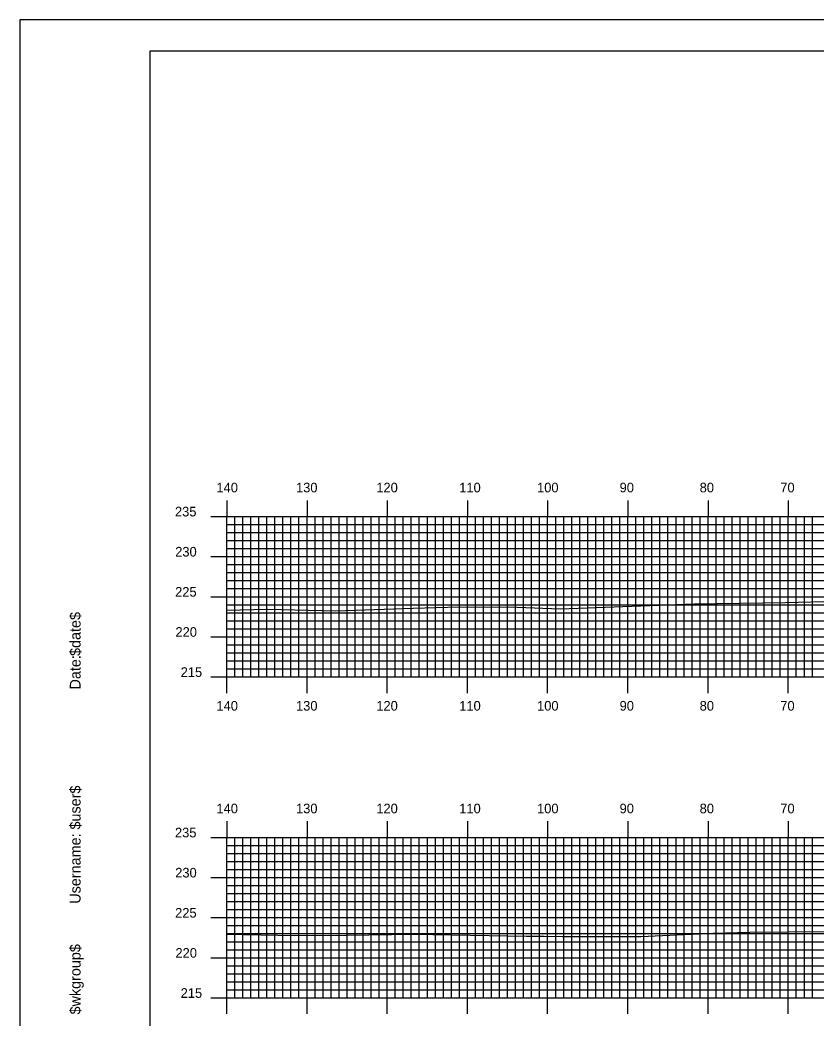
# Model space of a CAD drawing. Extents: x 1804684 to 1805027, y 442591 to 442811.
# Drawn here: x 1804683.9 to 1804783.1, y 442686.2 to 442810.5 of the extents above; entities that cross this region are included whole.
import ezdxf

# ---------------------------------------------------------------- set-up
doc = ezdxf.new("R2010")
doc.units = 0
for name, color, linetype in [('BORDER', 7, 'Continuous'), ('H_V ANNOTATION', 7, 'Continuous'), ('MAJOR', 7, 'Continuous'), ('MINOR', 7, 'Continuous'), ('PLOT BOUNDARY', 7, 'Continuous'), ('S_Roadway_Centerline', 7, 'Continuous')]:
    doc.layers.add(name, color=color, linetype=linetype)

msp = doc.modelspace()

# ---------------------------------------------------------------- linework, layer by layer
at = {"layer": 'BORDER'}
msp.add_lwpolyline([(1804700.08, 442596.67), (1805020.08, 442596.67), (1805020.08, 442806.67), (1804700.08, 442806.67)], close=True, dxfattribs=at)
at = {"layer": 'MAJOR'}
for p, q in [((1804709.68, 442750.67), (1804709.68, 442748.67)), ((1804719.68, 442750.67), (1804719.68, 442748.67)), ((1804729.68, 442750.67), (1804729.68, 442748.67)), ((1804739.68, 442750.67), (1804739.68, 442748.67)), ((1804749.68, 442750.67), (1804749.68, 442748.67)), ((1804759.68, 442750.67), (1804759.68, 442748.67)), ((1804769.68, 442750.67), (1804769.68, 442748.67)), ((1804779.68, 442750.67), (1804779.68, 442748.67)), ((1804707.68, 442748.67), (1804709.68, 442748.67)), ((1804709.68, 442748.67), (1804989.68, 442748.67)), ((1804709.68, 442728.67), (1804709.68, 442748.67)), ((1804709.68, 442728.67), (1804709.68, 442748.67)), ((1804709.68, 442748.67), (1804989.68, 442748.67)), ((1804719.68, 442728.67), (1804719.68, 442748.67)), ((1804729.68, 442728.67), (1804729.68, 442748.67)), ((1804739.68, 442728.67), (1804739.68, 442748.67)), ((1804749.68, 442728.67), (1804749.68, 442748.67)), ((1804759.68, 442728.67), (1804759.68, 442748.67)), ((1804769.68, 442728.67), (1804769.68, 442748.67)), ((1804779.68, 442728.67), (1804779.68, 442748.67)), ((1804707.68, 442743.67), (1804709.68, 442743.67)), ((1804709.68, 442743.67), (1804989.68, 442743.67)), ((1804707.68, 442738.67), (1804709.68, 442738.67)), ((1804709.68, 442738.67), (1804989.68, 442738.67)), ((1804707.68, 442733.67), (1804709.68, 442733.67)), ((1804709.68, 442733.67), (1804989.68, 442733.67)), ((1804707.68, 442728.67), (1804709.68, 442728.67)), ((1804709.68, 442728.67), (1804989.68, 442728.67)), ((1804709.68, 442728.67), (1804989.68, 442728.67)), ((1804709.68, 442726.66), (1804709.68, 442728.67)), ((1804719.68, 442726.66), (1804719.68, 442728.67)), ((1804729.68, 442726.66), (1804729.68, 442728.67)), ((1804739.68, 442726.66), (1804739.68, 442728.67)), ((1804749.68, 442726.66), (1804749.68, 442728.67)), ((1804759.68, 442726.66), (1804759.68, 442728.67)), ((1804769.68, 442726.66), (1804769.68, 442728.67)), ((1804779.68, 442726.66), (1804779.68, 442728.67)), ((1804709.68, 442710.67), (1804709.68, 442708.67)), ((1804719.68, 442710.67), (1804719.68, 442708.67)), ((1804729.68, 442710.67), (1804729.68, 442708.67)), ((1804739.68, 442710.67), (1804739.68, 442708.67)), ((1804749.68, 442710.67), (1804749.68, 442708.67)), ((1804759.68, 442710.67), (1804759.68, 442708.67)), ((1804769.68, 442710.67), (1804769.68, 442708.67)), ((1804779.68, 442710.67), (1804779.68, 442708.67)), ((1804707.68, 442708.67), (1804709.68, 442708.67)), ((1804709.68, 442708.67), (1804989.68, 442708.67)), ((1804709.68, 442688.67), (1804709.68, 442708.67)), ((1804709.68, 442688.67), (1804709.68, 442708.67)), ((1804709.68, 442708.67), (1804989.68, 442708.67)), ((1804719.68, 442688.67), (1804719.68, 442708.67)), ((1804729.68, 442688.67), (1804729.68, 442708.67)), ((1804739.68, 442688.67), (1804739.68, 442708.67)), ((1804749.68, 442688.67), (1804749.68, 442708.67)), ((1804759.68, 442688.67), (1804759.68, 442708.67)), ((1804769.68, 442688.67), (1804769.68, 442708.67)), ((1804779.68, 442688.67), (1804779.68, 442708.67)), ((1804707.68, 442703.67), (1804709.68, 442703.67)), ((1804709.68, 442703.67), (1804989.68, 442703.67)), ((1804707.68, 442698.67), (1804709.68, 442698.67)), ((1804709.68, 442698.67), (1804989.68, 442698.67)), ((1804707.68, 442693.67), (1804709.68, 442693.67)), ((1804709.68, 442693.67), (1804989.68, 442693.67)), ((1804707.68, 442688.67), (1804709.68, 442688.67)), ((1804709.68, 442688.67), (1804989.68, 442688.67)), ((1804709.68, 442688.67), (1804989.68, 442688.67)), ((1804709.68, 442686.66), (1804709.68, 442688.67)), ((1804719.68, 442686.66), (1804719.68, 442688.67)), ((1804729.68, 442686.66), (1804729.68, 442688.67)), ((1804739.68, 442686.66), (1804739.68, 442688.67)), ((1804749.68, 442686.66), (1804749.68, 442688.67)), ((1804759.68, 442686.66), (1804759.68, 442688.67)), ((1804769.68, 442686.66), (1804769.68, 442688.67)), ((1804779.68, 442686.66), (1804779.68, 442688.67))]:
    msp.add_line(p, q, dxfattribs=at)
at = {"layer": 'MINOR'}
for p, q in [((1804710.68, 442728.67), (1804710.68, 442748.67)), ((1804711.68, 442728.67), (1804711.68, 442748.67)), ((1804712.68, 442728.67), (1804712.68, 442748.67)), ((1804713.68, 442728.67), (1804713.68, 442748.67)), ((1804714.68, 442728.67), (1804714.68, 442748.67)), ((1804715.68, 442728.67), (1804715.68, 442748.67)), ((1804716.68, 442728.67), (1804716.68, 442748.67)), ((1804717.68, 442728.67), (1804717.68, 442748.67)), ((1804718.68, 442728.67), (1804718.68, 442748.67)), ((1804720.68, 442728.67), (1804720.68, 442748.67)), ((1804721.68, 442728.67), (1804721.68, 442748.67)), ((1804722.68, 442728.67), (1804722.68, 442748.67)), ((1804723.68, 442728.67), (1804723.68, 442748.67)), ((1804724.68, 442728.67), (1804724.68, 442748.67)), ((1804725.68, 442728.67), (1804725.68, 442748.67)), ((1804726.68, 442728.67), (1804726.68, 442748.67)), ((1804727.68, 442728.67), (1804727.68, 442748.67)), ((1804728.68, 442728.67), (1804728.68, 442748.67)), ((1804730.68, 442728.67), (1804730.68, 442748.67)), ((1804731.68, 442728.67), (1804731.68, 442748.67)), ((1804732.68, 442728.67), (1804732.68, 442748.67)), ((1804733.68, 442728.67), (1804733.68, 442748.67)), ((1804734.68, 442728.67), (1804734.68, 442748.67)), ((1804735.68, 442728.67), (1804735.68, 442748.67)), ((1804736.68, 442728.67), (1804736.68, 442748.67)), ((1804737.68, 442728.67), (1804737.68, 442748.67)), ((1804738.68, 442728.67), (1804738.68, 442748.67)), ((1804740.68, 442728.67), (1804740.68, 442748.67)), ((1804741.68, 442728.67), (1804741.68, 442748.67)), ((1804742.68, 442728.67), (1804742.68, 442748.67)), ((1804743.68, 442728.67), (1804743.68, 442748.67)), ((1804744.68, 442728.67), (1804744.68, 442748.67)), ((1804745.68, 442728.67), (1804745.68, 442748.67)), ((1804746.68, 442728.67), (1804746.68, 442748.67)), ((1804747.68, 442728.67), (1804747.68, 442748.67)), ((1804748.68, 442728.67), (1804748.68, 442748.67)), ((1804750.68, 442728.67), (1804750.68, 442748.67)), ((1804751.68, 442728.67), (1804751.68, 442748.67)), ((1804752.68, 442728.67), (1804752.68, 442748.67)), ((1804753.68, 442728.67), (1804753.68, 442748.67)), ((1804754.68, 442728.67), (1804754.68, 442748.67)), ((1804755.68, 442728.67), (1804755.68, 442748.67)), ((1804756.68, 442728.67), (1804756.68, 442748.67)), ((1804757.68, 442728.67), (1804757.68, 442748.67)), ((1804758.68, 442728.67), (1804758.68, 442748.67)), ((1804760.68, 442728.67), (1804760.68, 442748.67)), ((1804761.68, 442728.67), (1804761.68, 442748.67)), ((1804762.68, 442728.67), (1804762.68, 442748.67)), ((1804763.68, 442728.67), (1804763.68, 442748.67)), ((1804764.68, 442728.67), (1804764.68, 442748.67)), ((1804765.68, 442728.67), (1804765.68, 442748.67)), ((1804766.68, 442728.67), (1804766.68, 442748.67)), ((1804767.68, 442728.67), (1804767.68, 442748.67)), ((1804768.68, 442728.67), (1804768.68, 442748.67)), ((1804770.68, 442728.67), (1804770.68, 442748.67)), ((1804771.68, 442728.67), (1804771.68, 442748.67)), ((1804772.68, 442728.67), (1804772.68, 442748.67)), ((1804773.68, 442728.67), (1804773.68, 442748.67)), ((1804774.68, 442728.67), (1804774.68, 442748.67)), ((1804775.68, 442728.67), (1804775.68, 442748.67)), ((1804776.68, 442728.67), (1804776.68, 442748.67)), ((1804777.68, 442728.67), (1804777.68, 442748.67)), ((1804778.68, 442728.67), (1804778.68, 442748.67)), ((1804780.68, 442728.67), (1804780.68, 442748.67)), ((1804781.68, 442728.67), (1804781.68, 442748.67)), ((1804782.68, 442728.67), (1804782.68, 442748.67)), ((1804709.68, 442747.67), (1804989.68, 442747.67)), ((1804709.68, 442747.67), (1804711.68, 442747.67)), ((1804709.68, 442746.67), (1804989.68, 442746.67)), ((1804709.68, 442746.67), (1804711.68, 442746.67)), ((1804709.68, 442745.67), (1804989.68, 442745.67)), ((1804709.68, 442745.67), (1804711.68, 442745.67)), ((1804709.68, 442744.67), (1804989.68, 442744.67)), ((1804709.68, 442744.67), (1804711.68, 442744.67)), ((1804709.68, 442742.67), (1804989.68, 442742.67)), ((1804709.68, 442742.67), (1804711.68, 442742.67)), ((1804709.68, 442741.67), (1804989.68, 442741.67)), ((1804709.68, 442741.67), (1804711.68, 442741.67)), ((1804709.68, 442740.67), (1804989.68, 442740.67)), ((1804709.68, 442740.67), (1804711.68, 442740.67)), ((1804709.68, 442739.67), (1804989.68, 442739.67)), ((1804709.68, 442739.67), (1804711.68, 442739.67)), ((1804709.68, 442737.67), (1804989.68, 442737.67)), ((1804709.68, 442737.67), (1804711.68, 442737.67)), ((1804709.68, 442736.67), (1804989.68, 442736.67)), ((1804709.68, 442736.67), (1804711.68, 442736.67)), ((1804709.68, 442735.67), (1804989.68, 442735.67)), ((1804709.68, 442735.67), (1804711.68, 442735.67)), ((1804709.68, 442734.67), (1804989.68, 442734.67)), ((1804709.68, 442734.67), (1804711.68, 442734.67)), ((1804709.68, 442732.67), (1804989.68, 442732.67)), ((1804709.68, 442732.67), (1804711.68, 442732.67)), ((1804709.68, 442731.67), (1804989.68, 442731.67)), ((1804709.68, 442731.67), (1804711.68, 442731.67)), ((1804709.68, 442730.67), (1804989.68, 442730.67)), ((1804709.68, 442730.67), (1804711.68, 442730.67)), ((1804709.68, 442729.67), (1804989.68, 442729.67)), ((1804709.68, 442729.67), (1804711.68, 442729.67)), ((1804710.68, 442688.67), (1804710.68, 442708.67)), ((1804711.68, 442688.67), (1804711.68, 442708.67)), ((1804712.68, 442688.67), (1804712.68, 442708.67)), ((1804713.68, 442688.67), (1804713.68, 442708.67)), ((1804714.68, 442688.67), (1804714.68, 442708.67)), ((1804715.68, 442688.67), (1804715.68, 442708.67)), ((1804716.68, 442688.67), (1804716.68, 442708.67)), ((1804717.68, 442688.67), (1804717.68, 442708.67)), ((1804718.68, 442688.67), (1804718.68, 442708.67)), ((1804720.68, 442688.67), (1804720.68, 442708.67)), ((1804721.68, 442688.67), (1804721.68, 442708.67)), ((1804722.68, 442688.67), (1804722.68, 442708.67)), ((1804723.68, 442688.67), (1804723.68, 442708.67)), ((1804724.68, 442688.67), (1804724.68, 442708.67)), ((1804725.68, 442688.67), (1804725.68, 442708.67)), ((1804726.68, 442688.67), (1804726.68, 442708.67)), ((1804727.68, 442688.67), (1804727.68, 442708.67)), ((1804728.68, 442688.67), (1804728.68, 442708.67)), ((1804730.68, 442688.67), (1804730.68, 442708.67)), ((1804731.68, 442688.67), (1804731.68, 442708.67)), ((1804732.68, 442688.67), (1804732.68, 442708.67)), ((1804733.68, 442688.67), (1804733.68, 442708.67)), ((1804734.68, 442688.67), (1804734.68, 442708.67)), ((1804735.68, 442688.67), (1804735.68, 442708.67)), ((1804736.68, 442688.67), (1804736.68, 442708.67)), ((1804737.68, 442688.67), (1804737.68, 442708.67)), ((1804738.68, 442688.67), (1804738.68, 442708.67)), ((1804740.68, 442688.67), (1804740.68, 442708.67)), ((1804741.68, 442688.67), (1804741.68, 442708.67)), ((1804742.68, 442688.67), (1804742.68, 442708.67)), ((1804743.68, 442688.67), (1804743.68, 442708.67)), ((1804744.68, 442688.67), (1804744.68, 442708.67)), ((1804745.68, 442688.67), (1804745.68, 442708.67)), ((1804746.68, 442688.67), (1804746.68, 442708.67)), ((1804747.68, 442688.67), (1804747.68, 442708.67)), ((1804748.68, 442688.67), (1804748.68, 442708.67)), ((1804750.68, 442688.67), (1804750.68, 442708.67)), ((1804751.68, 442688.67), (1804751.68, 442708.67)), ((1804752.68, 442688.67), (1804752.68, 442708.67)), ((1804753.68, 442688.67), (1804753.68, 442708.67)), ((1804754.68, 442688.67), (1804754.68, 442708.67)), ((1804755.68, 442688.67), (1804755.68, 442708.67)), ((1804756.68, 442688.67), (1804756.68, 442708.67)), ((1804757.68, 442688.67), (1804757.68, 442708.67)), ((1804758.68, 442688.67), (1804758.68, 442708.67)), ((1804760.68, 442688.67), (1804760.68, 442708.67)), ((1804761.68, 442688.67), (1804761.68, 442708.67)), ((1804762.68, 442688.67), (1804762.68, 442708.67)), ((1804763.68, 442688.67), (1804763.68, 442708.67)), ((1804764.68, 442688.67), (1804764.68, 442708.67)), ((1804765.68, 442688.67), (1804765.68, 442708.67)), ((1804766.68, 442688.67), (1804766.68, 442708.67)), ((1804767.68, 442688.67), (1804767.68, 442708.67)), ((1804768.68, 442688.67), (1804768.68, 442708.67)), ((1804770.68, 442688.67), (1804770.68, 442708.67)), ((1804771.68, 442688.67), (1804771.68, 442708.67)), ((1804772.68, 442688.67), (1804772.68, 442708.67)), ((1804773.68, 442688.67), (1804773.68, 442708.67)), ((1804774.68, 442688.67), (1804774.68, 442708.67)), ((1804775.68, 442688.67), (1804775.68, 442708.67)), ((1804776.68, 442688.67), (1804776.68, 442708.67)), ((1804777.68, 442688.67), (1804777.68, 442708.67)), ((1804778.68, 442688.67), (1804778.68, 442708.67)), ((1804780.68, 442688.67), (1804780.68, 442708.67)), ((1804781.68, 442688.67), (1804781.68, 442708.67)), ((1804782.68, 442688.67), (1804782.68, 442708.67)), ((1804709.68, 442707.67), (1804989.68, 442707.67)), ((1804709.68, 442707.67), (1804711.68, 442707.67)), ((1804709.68, 442706.67), (1804989.68, 442706.67)), ((1804709.68, 442706.67), (1804711.68, 442706.67)), ((1804709.68, 442705.67), (1804989.68, 442705.67)), ((1804709.68, 442705.67), (1804711.68, 442705.67)), ((1804709.68, 442704.67), (1804989.68, 442704.67)), ((1804709.68, 442704.67), (1804711.68, 442704.67)), ((1804709.68, 442702.67), (1804989.68, 442702.67)), ((1804709.68, 442702.67), (1804711.68, 442702.67)), ((1804709.68, 442701.67), (1804989.68, 442701.67)), ((1804709.68, 442701.67), (1804711.68, 442701.67)), ((1804709.68, 442700.67), (1804989.68, 442700.67)), ((1804709.68, 442700.67), (1804711.68, 442700.67)), ((1804709.68, 442699.67), (1804989.68, 442699.67)), ((1804709.68, 442699.67), (1804711.68, 442699.67)), ((1804709.68, 442697.67), (1804989.68, 442697.67)), ((1804709.68, 442697.67), (1804711.68, 442697.67)), ((1804709.68, 442696.67), (1804989.68, 442696.67)), ((1804709.68, 442696.67), (1804711.68, 442696.67)), ((1804709.68, 442695.67), (1804989.68, 442695.67)), ((1804709.68, 442695.67), (1804711.68, 442695.67)), ((1804709.68, 442694.67), (1804989.68, 442694.67)), ((1804709.68, 442694.67), (1804711.68, 442694.67)), ((1804709.68, 442692.67), (1804989.68, 442692.67)), ((1804709.68, 442692.67), (1804711.68, 442692.67)), ((1804709.68, 442691.67), (1804989.68, 442691.67)), ((1804709.68, 442691.67), (1804711.68, 442691.67)), ((1804709.68, 442690.67), (1804989.68, 442690.67)), ((1804709.68, 442690.67), (1804711.68, 442690.67)), ((1804709.68, 442689.67), (1804989.68, 442689.67)), ((1804709.68, 442689.67), (1804711.68, 442689.67))]:
    msp.add_line(p, q, dxfattribs=at)
at = {"layer": 'PLOT BOUNDARY'}
msp.add_lwpolyline([(1804683.89, 442590.55), (1805023.89, 442590.55), (1805023.89, 442810.55), (1804683.89, 442810.55)], close=True, dxfattribs=at)
at = {"layer": 'S_Roadway_Centerline'}
for points in [[(1804709.68, 442736.98), (1804714.74, 442737.13), (1804723.26, 442736.9), (1804732.92, 442737.24), (1804738.63, 442737.39), (1804745.88, 442737.38), (1804751.24, 442737.16), (1804755.72, 442737.34), (1804767.98, 442737.78), (1804779.35, 442737.94), (1804785.69, 442738.12)], [(1804709.68, 442696.62), (1804718.15, 442696.44), (1804724.57, 442696.49), (1804733.05, 442696.6), (1804747.03, 442696.36), (1804749.26, 442696.36), (1804751.55, 442696.32), (1804761.29, 442696.31), (1804770.33, 442696.73), (1804774.87, 442696.86), (1804784.25, 442696.94)]]:
    msp.add_lwpolyline(points, dxfattribs=at)

# ---------------------------------------------------------------- texts
at = {"layer": 'BORDER'}
for s, p in [('$date$', (1804691.45, 442731.28)), ('Date:', (1804691.45, 442727.1)), ('$user$', (1804691.45, 442709.65)), ('Username:', (1804691.45, 442700.4)), ('$wkgroup$', (1804691.45, 442686.6))]:
    msp.add_text(s, height=1.339, rotation=90, dxfattribs=at).set_placement(p)
at = {"layer": 'H_V ANNOTATION'}
for s, p in [('140', (1804708.39, 442751.67)), ('130', (1804718.31, 442751.67)), ('120', (1804728.32, 442751.67)), ('110', (1804738.66, 442751.67)), ('100', (1804748.36, 442751.67)), ('90', (1804758.65, 442751.67)), ('80', (1804768.63, 442751.67)), ('70', (1804778.68, 442751.67)), ('235', (1804703.22, 442748.67)), ('230', (1804703.25, 442743.67)), ('225', (1804703.24, 442738.67)), ('220', (1804703.28, 442733.67)), ('215', (1804703.93, 442728.67)), ('140', (1804708.39, 442724.47)), ('130', (1804718.31, 442724.47)), ('120', (1804728.32, 442724.47)), ('110', (1804738.66, 442724.47)), ('100', (1804748.36, 442724.47)), ('90', (1804758.65, 442724.47)), ('80', (1804768.63, 442724.47)), ('70', (1804778.68, 442724.47)), ('140', (1804708.39, 442711.67)), ('130', (1804718.31, 442711.67)), ('120', (1804728.32, 442711.67)), ('110', (1804738.66, 442711.67)), ('100', (1804748.36, 442711.67)), ('90', (1804758.65, 442711.67)), ('80', (1804768.63, 442711.67)), ('70', (1804778.68, 442711.67)), ('235', (1804703.22, 442708.67)), ('230', (1804703.25, 442703.67)), ('225', (1804703.24, 442698.67)), ('220', (1804703.28, 442693.67)), ('215', (1804703.93, 442688.67))]:
    msp.add_text(s, height=1.2, dxfattribs=at).set_placement(p)
at = {"layer": 'MAJOR'}
for p in [(1804709.67, 442728.67), (1804709.67, 442688.67)]:
    msp.add_text('-', height=0.012, dxfattribs=at).set_placement(p)

doc.saveas('drawing.dxf')
